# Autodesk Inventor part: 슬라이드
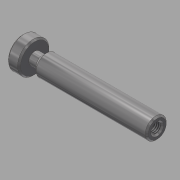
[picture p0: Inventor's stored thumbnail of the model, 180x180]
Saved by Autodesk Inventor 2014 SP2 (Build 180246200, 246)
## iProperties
Created: 2015-12
Part Number: 슬라이드
Document SubType Name: Modeling
Designer: mdu
Density: 8.08 g/cm^3
Material: 스테인리스강
Appearance: 반광택
Mass: 114.493 g
Surface Area: 49.8963 cm^2
Volume: 14.17 cm^3
Author: mdu
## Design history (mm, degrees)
sketch "스케치1"
  geometry: L1 (-45, 0)-(45, 0); L2 (-45, 0)-(-45, 10.5); L3 (-45, 10.5)-(-37, 10.5); L4 (-37, 10.5)-(-37, 4); L5 (-37, 4)-(-32, 4); L6 (-32, 4)-(-29, 7); L7 (-29, 7)-(45, 7); L8 (45, 7)-(45, 0); 2 further points
  constraints: 16 end point, 4 parallel, 2 perpendicular, 1 coincident, 1 horizontal, 1 midpoint
  dimensions: "d0" = 90 distance of L1.start L1.end; "d1" = 21 diameter of L3 L1; "d2" = 14 diameter of L7 L1; "d3" = 8 diameter of L5 L1; "d4" = 8 distance of L2.end L3.end; "d5" = 5 distance of L4.end L5.end; "d6" = 135 deg angle of L6 L5
revolve "회전1" sketch "스케치1" stored, may be unused: angle "d7" = 90 deg
chamfer "모따기1" distance "d8" = 1; stored, may be unused: second distance "d9" = 2, angle "d10" = 45 deg
hole "구멍1" diameter "d13" = 6.647; stored, may be unused: countersink angle "d17" = 90 deg, drill point angle "d19" = 118 deg; dims "d11" = 10, "d12" = 10, "d14" = 9, "d15" = 4, "d16" = 2, "d18" = 12
chamfer "모따기2" distance "d20" = 1; stored, may be unused: second distance "d21" = 2, angle "d22" = 45 deg
node "솔리드1"
